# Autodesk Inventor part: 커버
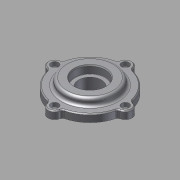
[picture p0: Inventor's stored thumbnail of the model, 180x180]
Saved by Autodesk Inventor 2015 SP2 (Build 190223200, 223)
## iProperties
Company: 한국ATC센터
Created: 2015-12
Part Number: 커버
Document SubType Name: Modeling
Designer: mdu
Density: 1 g/cm^3
Material: 일반
Appearance: 기본값
Author: mdu
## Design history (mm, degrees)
sketch "스케치1"
  geometry: C1 r 1.621 at (0, 6.75) reference; C2 r 1.621 at (-37, -30.25) reference; C3 r 1.621 at (0, -67.25) reference; C4 r 1.621 at (37, -30.25) reference; C5 r 10 at (0, -30.25) reference; C6 r 12 at (0, -30.25); C7 r 24.5 at (0, -30.25) reference; A1 r 3 centre (-38.77, -20.408) between (-38.239, -23.361) and (-35.862, -21.146) reference; A2 r 7 centre (-37, -30.25) between (-38.239, -23.361) and (-38.239, -37.139) reference; A3 r 3 centre (-38.77, -40.092) between (-35.862, -39.354) and (-38.239, -37.139) reference; A4 r 37 centre (0, -30.25) between (-35.862, -39.354) and (-9.104, -66.113) reference; A5 r 3 centre (-9.842, -69.02) between (-6.889, -68.489) and (-9.104, -66.113) reference; A6 r 7 centre (0, -67.25) between (-6.889, -68.489) and (6.889, -68.489) reference; A7 r 3 centre (9.842, -69.02) between (9.104, -66.112) and (6.889, -68.489) reference; A8 r 37 centre (0, -30.25) between (9.104, -66.112) and (35.863, -39.354) reference; A9 r 3 centre (38.77, -40.092) between (38.239, -37.139) and (35.863, -39.354) reference; A10 r 7 centre (37, -30.25) between (38.239, -37.139) and (38.239, -23.361) reference; A11 r 3 centre (38.77, -20.408) between (35.863, -21.146) and (38.239, -23.361) reference; A12 r 37 centre (0, -30.25) between (35.863, -21.146) and (9.104, 5.612) reference; A13 r 3 centre (9.842, 8.52) between (6.889, 7.989) and (9.104, 5.612) reference; A14 r 7 centre (0, 6.75) between (6.889, 7.989) and (-6.889, 7.989) reference; A15 r 3 centre (-9.842, 8.52) between (-9.104, 5.612) and (-6.889, 7.989) reference; A16 r 37 centre (0, -30.25) between (-9.104, 5.612) and (-35.862, -21.146) reference; 1 further point
  constraints: 1 centre point, 1 coincident
  dimensions: "d2" = 2 radial gap between concentric circles of C6 C5
extrude "돌출1" new body sketch "스케치1" distance "d0" = 8; taper "d1" = 0 deg
sketch "스케치2"
  geometry: C1 r 23.5 at (0, -30.25) reference; C2 r 12 at (0, -30.25) reference; 1 further point
extrude "돌출2" join sketch "스케치2" distance "d4" = 5; taper "d5" = 0 deg
sketch "스케치3"
  geometry: C1 r 23.5 at (0, 0) reference; C2 r 20.5 at (0, 0); 1 further point
  constraints: 1 centre point
  dimensions: "d6" = 3 radial gap between concentric circles of C2 C1
node "작업 평면1"
extrude "돌출3" join sketch "스케치3" stored distance "d7" = 5; taper "d8" = 0 deg
fillet "모깎기1" dims "d9" = 3
sketch "스케치4"
  geometry: C1 r 12 at (0, -30.25) reference; C2 r 27 at (0, -30.25); 1 further point
  constraints: 1 centre point
  dimensions: "d10" = 15 radial gap between concentric circles of C1 C2
extrude "돌출4" join sketch "스케치4" distance "d11" = 7; taper "d12" = 0 deg
fillet "모깎기2" dims "d13" = 3
chamfer "모따기1" distance "d14" = 1; stored, may be unused: second distance "d15" = 2, angle "d16" = 45 deg
node "작업점1"
  node "작업축1"
chamfer "모따기2" distance "d24" = 1; stored, may be unused: second distance "d25" = 2, angle "d26" = 45 deg
hole "구멍6" diameter "d43" = 4.5; stored, may be unused: countersink angle "d47" = 90 deg, drill point angle "d49" = 118 deg; dims "d41" = 10, "d42" = 10, "d44" = 6, "d45" = 8, "d46" = 4.4, "d48" = 8
sketch "스케치8"
  geometry: C1 r 12 at (0, 0) reference; C2 r 16 at (0, 0); 1 further point
  constraints: 1 centre point, 1 coincident
  dimensions: "d53" = 32 diameter of C2
extrude "돌출5" cut sketch "스케치8" distance "d54" = 8.3; taper "d55" = 0 deg
fillet "모깎기3" dims "d56" = 0.3
chamfer "모따기3" distance "d57" = 1.2; stored, may be unused: second distance "d58" = 2, angle "d59" = 30 deg
node "솔리드1"
pattern_circular "원형 패턴1" dims angle "d51" = 360 deg
node "참조1"
node "참조2"
